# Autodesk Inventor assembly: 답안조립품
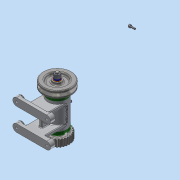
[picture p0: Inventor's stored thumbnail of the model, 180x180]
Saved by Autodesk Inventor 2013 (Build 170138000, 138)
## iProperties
Created: 2015-11
Part Number: 답안조립품
Document SubType Name: Assembly
Designer: Administrator
Author: Administrator
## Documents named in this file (16)
- C:\Users\Administrator\Desktop\451110V1044\답안조립품.iam
- C:\Users\Administrator\Desktop\451110V1044\본체.ipt
- C:\Users\Administrator\Desktop\451110V1044\V벨트풀리.ipt
- C:\Users\Administrator\Desktop\451110V1044\너트 M 8.ipt
- C:\Users\Administrator\Desktop\451110V1044\니플 M 6 x 0.75.ipt
- C:\Users\Administrator\Desktop\451110V1044\베어링 15 x 32 x 9.ipt
- C:\Users\Administrator\Desktop\451110V1044\볼트 M 6 x 8.ipt
- C:\Users\Administrator\Desktop\451110V1044\볼트 M4 x 12.ipt
- C:\Users\Administrator\Desktop\451110V1044\스퍼기어.ipt
- C:\Users\Administrator\Desktop\451110V1044\스프링와셔 8.ipt
- C:\Users\Administrator\Desktop\451110V1044\오일 실 15 25 7.ipt
- C:\Users\Administrator\Desktop\451110V1044\와셔 6x11.5.ipt
- C:\Users\Administrator\Desktop\451110V1044\와셔 8x17.ipt
- C:\Users\Administrator\Desktop\451110V1044\축.ipt
- C:\Users\Administrator\Desktop\451110V1044\커버.ipt
- C:\Users\Administrator\Desktop\451110V1044\키 3 x 3 x 12.ipt
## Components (4 placed, 3 different names)
1. KS B 2023 6002 - 15 x 32 x 9:1
2. ISO 4762 M4 x 12:1
3. V벨트풀리:2
4. KS B 2023 6002 - 15 x 32 x 9:2
